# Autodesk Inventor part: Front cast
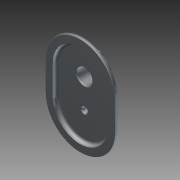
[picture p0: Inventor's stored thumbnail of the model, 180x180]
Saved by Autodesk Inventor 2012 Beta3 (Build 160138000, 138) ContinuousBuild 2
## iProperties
Created: 2010-12
Part Number: Front cast
Document SubType Name: Modeling
Designer: Thom Tremblay
Density: 7.25 g/cm^3
Material: Cast Iron
Mass: 515.624 g
Surface Area: 438.513 cm^2
Volume: 71.1205 cm^3
Author: Thom Tremblay
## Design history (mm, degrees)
sketch "Sketch1"
  geometry: L1 (-50, -50)-(-50, 0); L2 (50, 0)-(50, -50); L3 (-60, 0)-(-60, -50); L4 (60, -50)-(60, 0); A1 r 50 centre (0, 0) between (50, 0) and (-50, 0); A2 r 50 centre (0, -50) between (-50, -50) and (50, -50); A3 r 60 centre (0, -50) between (-60, -50) and (60, -50); A4 r 60 centre (0, 0) between (60, 0) and (-60, 0); 1 further point
  constraints: 8 end point, 8 point on circle, 4 centre point, 4 tangent, 2 parallel, 1 coincident, 1 vertical, 3 other
  dimensions: "d0" = 50 distance of L2.start L2.end; "d1" = 50 radius of A1; "d2" = 10 radial gap between concentric circles of A4 A1
extrude "Extrusion1" new body sketch "Sketch1" distance "d3" = 10; taper "d4" = -2 deg
fillet "Fillet1" dims "d7" = 8
shell "Shell3" dims "d142" = 3
extrude "Extrusion2" join sketch "Sketch1" distance "d5" = 5; taper "d6" = -2 deg
fillet "Fillet2" dims "d9" = 1.5, "d10" = 1
sketch "Sketch7"
  geometry: C1 r 22.5 at (0, 0); 1 further point
  constraints: 1 centre point, 1 coincident
  dimensions: "d63" = 45 diameter of C1
extrude "Extrusion8" join sketch "Sketch7" distance "d64" = 24; taper "d65" = -2 deg
fillet "Fillet11" dims "d75" = 3
sketch "Sketch8"
  geometry: C1 r 12.5 at (0, -50); A1 r 60 centre (0, -50) between (-60, -50) and (60, -50) reference; 1 further point
  constraints: 1 centre point, 1 coincident
  dimensions: "d76" = 25 diameter of C1
extrude "Extrusion9" join sketch "Sketch8" distance "d77" = 12; taper "d78" = -2 deg; dims "d89" = 8, "d90" = -2 deg
fillet "Fillet12" dims "d79" = 3
sketch "Sketch9" dims "d91" = 45
  geometry: L1 (0, 0)-(0, 22.5); C1 r 4 at (0, 22.5); 1 further point
  constraints: 2 end point, 1 centre point, 1 coincident, 1 vertical, 1 vertical alignment, 2 other
  dimensions: "d92" = 8 diameter of C1
extrude "Extrusion10" join sketch "Sketch9" stored distance "d95" = 0; taper "d96" = 2 deg
sketch "Sketch12"
  geometry: C1 r 5 at (0, 0); A1 r 41.925 centre (0, 0) between (-41.925, 0) and (41.925, 0) reference
  constraints: 1 centre point, 1 coincident
  dimensions: "d136" = 10 diameter of C1
extrude "Extrusion11" cut sketch "Sketch12" distance "d137" = 8; taper "d138" = -2 deg
fillet "Fillet13" dims "d97" = 3
pattern_circular "Circular Pattern2" dims angle "d133" = 360 deg
sketch "Sketch13"
  geometry: C1 r 13 at (0, 50); A1 r 41.925 centre (0, 50) between (41.925, 50) and (-41.925, 50) reference
  constraints: 1 centre point, 1 coincident
  dimensions: "d139" = 26 diameter of C1
extrude "Extrusion12" cut sketch "Sketch13" stored distance "d140" = 10; taper "d141" = 2 deg
fillet "Fillet14" dims "d135" = 2
fillet "Fillet15" dims "d143" = 2
body "Solid1"
